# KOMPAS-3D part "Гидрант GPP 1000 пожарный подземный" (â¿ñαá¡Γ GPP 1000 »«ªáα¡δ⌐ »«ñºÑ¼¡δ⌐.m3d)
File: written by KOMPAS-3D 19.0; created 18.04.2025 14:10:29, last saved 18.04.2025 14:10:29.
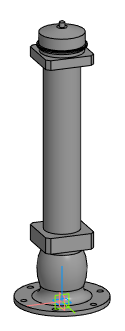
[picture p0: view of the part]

Document properties: Полное имя файла: E:\Dendor Работа Сачек\3D для проекитирвщиков\11.1 Тип GPP. Гидрант пожарный подземный\stp_Тип GPP. 750-6000 Гидрант пожарный подземный\Гидрант GPP 1000 пожарный подземный.m3d

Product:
- Part/product: Гидрант GPP 1000 пожарный подземный

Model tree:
1. Операция без истории:1  (labels: Гидрант GPP 1000 пожарный подземный)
